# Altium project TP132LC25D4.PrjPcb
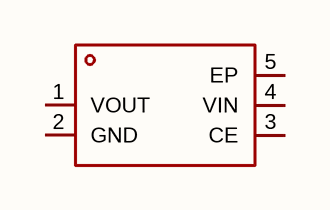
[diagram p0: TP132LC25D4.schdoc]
1 sheet, 1 parts. Net scope: global (net labels, ports and power ports of the same name join across sheets).

## Sheet TP132LC25D4.schdoc
size 127 x 101 mm

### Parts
U?  tp132lc25d4  [UDFN-4_L1.0-W1.0-P0.65-BL-EP]  (value not drawn)

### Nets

Not connected (* = marked no-connect by the designer): U? 1(VOUT) 2(GND) 3(CE) 4(VIN) 5(EP)

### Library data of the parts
U? = tp132lc25d4: 输出极性:正极;工作电压:7V;输出电压:2.5V;输出电流:300mA;电源纹波抑制比(PSRR):70dB@(1kHz);输出类型:固定;; Manufacturer: TECH PUBLIC(台舟); AddInBom: yes; ModelId: c1a489df884542e2aa77aee3d93f92e3; ModelName: UDFN-4_L1.0-W1.0-H0.6-P0.65-BL-EP; ModelTransform: 40.1574,40.1574,0,0,0,0,0,0,0; Output Configuration: 正极; Voltage - Supply: 7V; Output Voltage: 2.5V; Output Current: 300mA; standby current: 800nA; Output Type: 固定; Number of Outputs: 1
